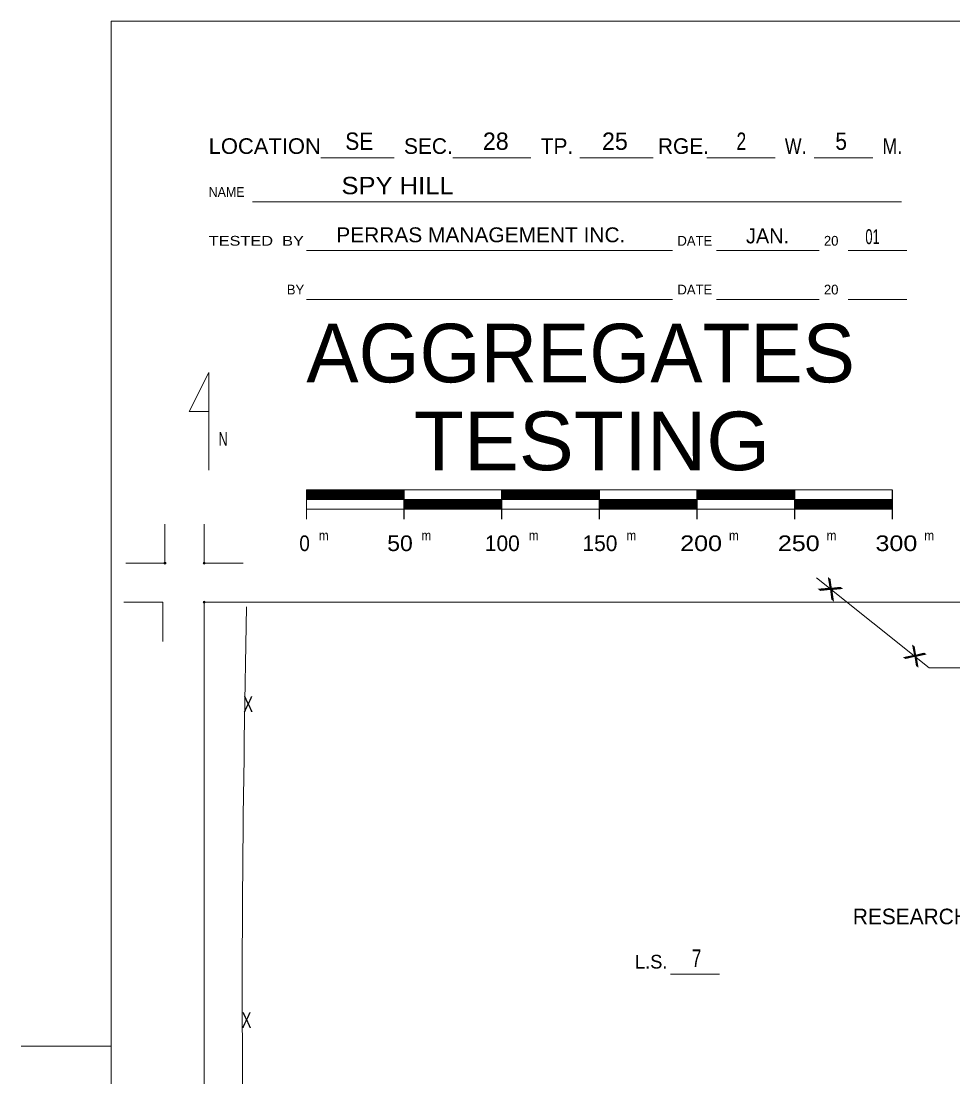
# Model space of a CAD drawing. Extents: x -496 to 480, y -450 to 700.
# Drawn here: x -496 to -19, y 159 to 700 of the extents above; entities that cross this region are included whole.
import ezdxf
from ezdxf.enums import TextEntityAlignment as Align

# ---------------------------------------------------------------- set-up
doc = ezdxf.new("R2010")
doc.units = 0
doc.header["$LTSCALE"] = 2
doc.header["$PDMODE"] = 32
doc.header["$PDSIZE"] = 1
for name, color, linetype, lineweight in [('1', 7, 'Continuous', 13), ('3', 7, 'Continuous', 13), ('4', 7, 'Continuous', 25)]:
    doc.layers.add(name, color=color, linetype=linetype, lineweight=lineweight)

msp = doc.modelspace()

# ---------------------------------------------------------------- linework, layer by layer
at = {"layer": '1'}
for p, q in [((-342.517, 629.973), (-305.017, 629.973)), ((-275.017, 629.973), (-235.017, 629.973)), ((-210.017, 629.973), (-172.517, 629.973)), ((-145.017, 629.973), (-110.017, 629.973)), ((-90.017, 629.973), (-60.017, 629.973)), ((-377.517, 607.473), (-45.359, 607.473)), ((-350.017, 582.473), (-162.517, 582.473)), ((-140.017, 582.473), (-87.517, 582.473)), ((-72.517, 582.473), (-42.517, 582.473)), ((-350.017, 557.473), (-162.517, 557.473)), ((-140.017, 557.473), (-87.517, 557.473)), ((-72.517, 557.473), (-42.517, 557.473)), ((-350.017, 459.973), (-350.017, 444.973)), ((-50.017, 459.973), (-350.017, 459.973)), ((-350.017, 454.973), (-50.017, 454.973)), ((-422.391, 422.339), (-422.391, 442.339)), ((-402.391, 422.339), (-402.391, 442.339)), ((-422.391, 422.339), (-442.391, 422.339)), ((-423.537, 402.339), (-443.537, 402.339)), ((-423.537, 402.339), (-423.537, 382.339)), ((-402.391, 402.339), (-402.391, -402.333)), ((-382.391, 402.339), (-402.391, 402.339)), ((-163.533, 211.85), (-138.533, 211.85)), ((-450.017, 174.973), (-496.057, 174.973))]:
    msp.add_line(p, q, dxfattribs=at)
at = {"layer": '1', "lineweight": 25}
for p, q in [((-300.017, 459.973), (-300.017, 444.973)), ((-250.017, 459.973), (-250.017, 444.973)), ((-200.017, 459.973), (-200.017, 444.973)), ((-150.017, 459.973), (-150.017, 444.973)), ((-100.017, 459.973), (-100.017, 444.973)), ((-50.017, 459.973), (-50.017, 444.973)), ((-350.017, 459.473), (-300.017, 459.473)), ((-350.017, 458.973), (-300.017, 458.973)), ((-350.017, 458.473), (-300.017, 458.473)), ((-350.017, 457.973), (-300.017, 457.973)), ((-350.017, 457.473), (-300.017, 457.473)), ((-350.017, 456.973), (-300.017, 456.973)), ((-350.017, 456.473), (-300.017, 456.473)), ((-350.017, 456.473), (-300.017, 456.473)), ((-350.017, 456.473), (-300.017, 456.473)), ((-350.017, 455.973), (-300.017, 455.973)), ((-350.017, 455.973), (-300.017, 455.973)), ((-350.017, 455.473), (-300.017, 455.473)), ((-300.017, 454.473), (-250.017, 454.473)), ((-250.017, 459.473), (-200.017, 459.473)), ((-250.017, 458.973), (-200.017, 458.973)), ((-250.017, 458.473), (-200.017, 458.473)), ((-250.017, 457.973), (-200.017, 457.973)), ((-250.017, 457.473), (-200.017, 457.473)), ((-250.017, 456.973), (-200.017, 456.973)), ((-250.017, 456.473), (-200.017, 456.473)), ((-250.017, 455.973), (-200.017, 455.973)), ((-250.017, 455.473), (-200.017, 455.473)), ((-200.017, 454.473), (-150.017, 454.473)), ((-150.017, 459.473), (-100.017, 459.473)), ((-150.017, 458.973), (-100.017, 458.973)), ((-150.017, 458.473), (-100.017, 458.473)), ((-150.017, 457.973), (-100.017, 457.973)), ((-150.017, 457.473), (-100.017, 457.473)), ((-150.017, 456.973), (-100.017, 456.973)), ((-150.017, 456.473), (-100.017, 456.473)), ((-150.017, 455.973), (-100.017, 455.973)), ((-150.017, 455.473), (-100.017, 455.473)), ((-100.017, 454.473), (-50.017, 454.473)), ((-300.017, 453.973), (-250.017, 453.973)), ((-300.017, 453.473), (-250.017, 453.473)), ((-300.017, 452.973), (-250.017, 452.973)), ((-300.017, 452.473), (-250.017, 452.473)), ((-300.017, 451.973), (-250.017, 451.973)), ((-300.017, 451.473), (-250.017, 451.473)), ((-300.017, 450.973), (-250.017, 450.973)), ((-300.017, 450.473), (-250.017, 450.473)), ((-200.017, 453.973), (-150.017, 453.973)), ((-200.017, 453.473), (-150.017, 453.473)), ((-200.017, 452.973), (-150.017, 452.973)), ((-200.017, 452.473), (-150.017, 452.473)), ((-200.017, 451.973), (-150.017, 451.973)), ((-200.017, 451.473), (-150.017, 451.473)), ((-200.017, 450.973), (-150.017, 450.973)), ((-200.017, 450.473), (-150.017, 450.473)), ((-100.017, 453.973), (-50.017, 453.973)), ((-100.017, 453.473), (-50.017, 453.473)), ((-100.017, 452.973), (-50.017, 452.973)), ((-100.017, 452.473), (-50.017, 452.473)), ((-100.017, 451.973), (-50.017, 451.973)), ((-100.017, 451.473), (-50.017, 451.473)), ((-100.017, 450.973), (-50.017, 450.973)), ((-100.017, 450.473), (-50.017, 450.473))]:
    msp.add_line(p, q, dxfattribs=at)
at = {"layer": '1'}
for points in [[(449.983, -450.027), (449.983, 399.973), (449.983, 699.973), (-450.017, 699.973), (-450.017, 49.973), (-450.017, -450.027)], [(-400.017, 469.973), (-400.017, 519.973), (-410.017, 499.973), (-400.017, 499.973)], [(-350.017, 449.973), (-50.017, 449.973), (-50.017, 459.973)], [(-402.391, 422.339), (-382.391, 422.339), (-402.391, 422.339)], [(402.281, -402.333), (402.281, 402.339), (-402.391, 402.339)]]:
    msp.add_lwpolyline(points, dxfattribs=at)
for p in [(-422.391, 422.339), (-402.391, 422.339), (-402.391, 402.339)]:
    msp.add_point(p, dxfattribs=at)
at = {"layer": '3'}
msp.add_line((-31.099, 368.814), (-88.767, 414.926), dxfattribs=at)
msp.add_lwpolyline([(397.281, 379.989), (164.621, 379.989), (150.641, 368.814), (-31.099, 368.814)], dxfattribs=at)
msp.add_spline([(-372.604, -109.817), (-381.459, 90.018), (-380.682, 399.949)], degree=3, dxfattribs=at)

# ---------------------------------------------------------------- texts
at = {"layer": '1'}
for s, height, width, p in [('LOCATION', 8, 1.05, (-400.017, 631.973)), ('W.', 8, 0.85, (-105.017, 631.973)), ('M.', 8, 0.85, (-55.017, 631.973)), ('NAME', 5, 0.95, (-400.017, 609.973)), ('TESTED  BY', 5, 1.25, (-400.017, 584.973)), ('TESTING', 30, 1.05, (-295.017, 469.973)), ('N', 7, 0.7, (-395.017, 482.473)), ('m', 5, 0.9, (-343.607, 434.073)), ('m', 5, 0.9, (-291.107, 434.073)), ('m', 5, 0.9, (-236.107, 434.073)), ('m', 5, 0.9, (-186.107, 434.073)), ('m', 5, 0.9, (-133.607, 434.073)), ('m', 5, 0.9, (-83.607, 434.073)), ('m', 5, 0.9, (-33.607, 434.073)), ('0', 8, 0.9, (-353.607, 428.573)), ('50', 8, 1.1, (-308.607, 428.573)), ('200', 8, 1.2, (-158.607, 428.573)), ('250', 8, 1.2, (-108.607, 428.573)), ('300', 8, 1.2, (-58.607, 428.573))]:
    msp.add_text(s, height=height, dxfattribs=dict(at, width=width)).set_placement(p)
for s, height, width, p in [('SE', 8.89, 0.9, (-322.943, 634.038)), ('2', 8.89, 0.75, (-127.28, 634.037)), ('5', 8.89, 0.9, (-76.181, 634.038)), ('SPY HILL', 8.89, 1.1, (-303.323, 611.329)), ('PERRAS MANAGEMENT INC.', 7.62, 1.05, (-260.682, 586.728)), ('01', 7.62, 0.65, (-60.119, 585.781)), ('7', 8.89, 0.75, (-150.235, 215.639))]:
    msp.add_text(s, height=height, dxfattribs=dict(at, width=width)).set_placement(p, align=Align.CENTER)
for s, height, p in [('SEC.', 8, (-300.017, 631.973)), ('TP.', 8, (-230.017, 631.973)), ('RGE.', 8, (-170.017, 631.973)), ('DATE', 5, (-160.017, 584.973)), ('20', 5, (-85.017, 584.973)), ('BY', 5, (-360.017, 559.973)), ('DATE', 5, (-160.017, 559.973)), ('20', 5, (-85.017, 559.973)), ('AGGREGATES', 30, (-350.017, 514.973)), ('100', 8, (-258.607, 428.573)), ('150', 8, (-208.607, 428.573))]:
    msp.add_text(s, height=height, dxfattribs=at).set_placement(p)
for s, height, p in [('28', 8.89, (-253.021, 634.038)), ('25', 8.89, (-192.027, 634.038)), ('JAN.', 7.62, (-113.875, 586.148)), ('L.S.', 7, (-173.44, 214.794))]:
    msp.add_text(s, height=height, dxfattribs=at).set_placement(p, align=Align.CENTER)
at = {"layer": '3'}
for rotation, width, p in [(321.849, 1.6, (-84.049, 405.972)), (326.292, 1.45, (-40.574, 371.51))]:
    msp.add_text('X', height=8, rotation=rotation, dxfattribs=dict(at, width=width)).set_placement(p, align=Align.CENTER)
at = {"layer": '3', "width": 0.7}
for p in [(-379.798, 346.102), (-380.64, 184.364)]:
    msp.add_text('X', height=8, dxfattribs=at).set_placement(p, align=Align.CENTER)
at = {"layer": '4'}
msp.add_text('RESEARCH CENTER', height=8, dxfattribs=at).set_placement((-17.025, 237.444), align=Align.CENTER)

doc.saveas('drawing.dxf')
